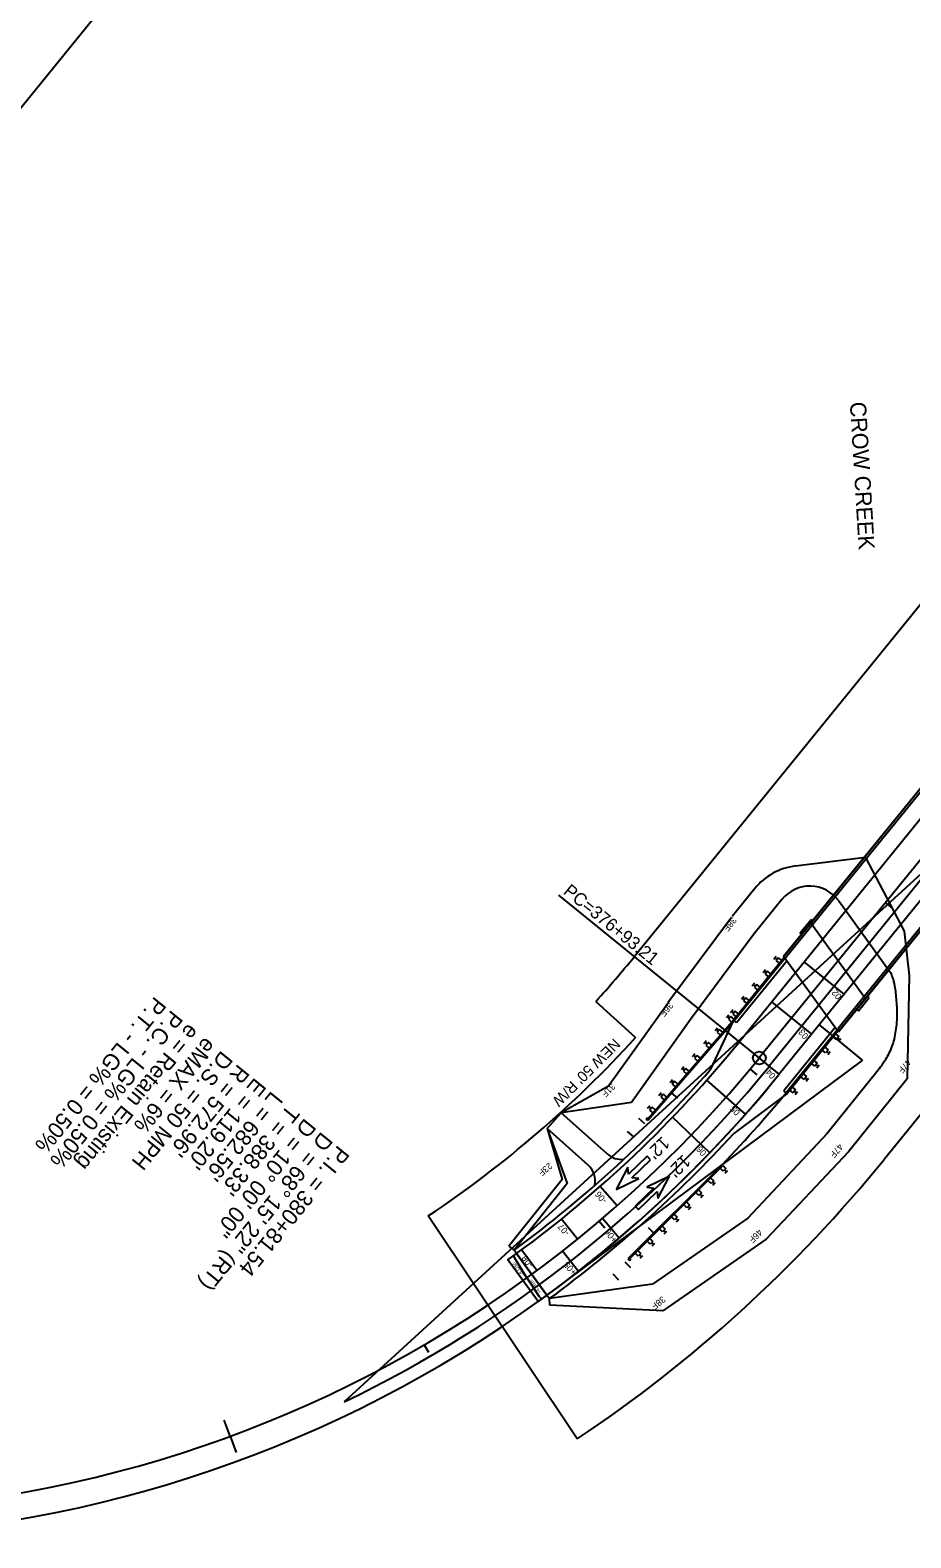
# Model space of a CAD drawing. Extents: x 144 to 1452322, y 4017 to 1128039.
# Drawn here: x 1450309 to 1450719, y 1126638 to 1127341 of the extents above; entities that cross this region are included whole.
import ezdxf

# ---------------------------------------------------------------- set-up
doc = ezdxf.new("R2010")
doc.units = 0
for name, color, linetype in [('BR_CONCRETE', 7, 'Continuous'), ('BR_PROPOSED_TRAVELWAY', 7, 'Continuous'), ('RD_HC_Cl', 7, 'Continuous'), ('RD_HC_Data', 7, 'Continuous'), ('RD_HC_Data_Tic', 7, 'Continuous'), ('RD_PD_ALT1_TX', 7, 'Continuous'), ('RD_PD_BOC', 7, 'Continuous'), ('RD_PD_CstnLmt', 7, 'Continuous'), ('RD_PD_CstnLmt_TX', 7, 'Continuous'), ('RD_PD_DR_ErosCtrl', 7, 'Continuous'), ('RD_PD_Driveway', 7, 'Continuous'), ('RD_PD_EOP', 7, 'Continuous'), ('RD_PD_Final_TrvlWay', 7, 'Continuous'), ('RD_PD_Final_TX', 7, 'Continuous'), ('RD_PD_FOC', 7, 'Continuous'), ('RD_PD_GR', 7, 'Continuous'), ('RD_PD_PaveShd', 7, 'Continuous'), ('RD_PD_RW', 7, 'Continuous'), ('RD_SHT_ShtClip', 7, 'Continuous'), ('RD_Sketch8', 7, 'Continuous'), ('RD_Sketch9', 7, 'Continuous'), ('RD_SMD_Locator', 7, 'Continuous'), ('RD_TX_Pipe_ElevEX', 7, 'Continuous')]:
    doc.layers.add(name, color=color, linetype=linetype)

# ---------------------------------------------------------------- blocks, each defined once
blk = doc.blocks.new('Guardrail_MTBBC3_Transition')
at = {"layer": 'RD_PD_GR'}
for p, q in [((37, 0.5), (0, 0.5)), ((0, 0.5), (0, 0)), ((0, 0), (37, 0)), ((3.525, 3.75), (1.775, 3.75)), ((1.775, 0.5), (1.775, 2.5)), ((1.775, 2.5), (3.525, 2.5)), ((3.525, 0.5), (1.775, 0.5)), ((2.65, 2.5), (2.65, 3.75)), ((3.525, 2.5), (3.525, 0.5)), ((11.525, 3.75), (9.775, 3.75)), ((9.775, 0.5), (9.775, 2.5)), ((9.775, 2.5), (11.525, 2.5)), ((11.525, 0.5), (9.775, 0.5)), ((10.65, 2.5), (10.65, 3.75)), ((11.525, 2.5), (11.525, 0.5)), ((19.525, 3.75), (17.775, 3.75)), ((17.775, 0.5), (17.775, 2.5)), ((17.775, 2.5), (19.525, 2.5)), ((19.525, 0.5), (17.775, 0.5)), ((18.65, 2.5), (18.65, 3.75)), ((19.525, 2.5), (19.525, 0.5)), ((27.525, 3.75), (25.775, 3.75)), ((25.775, 0.5), (25.775, 2.5)), ((25.775, 2.5), (27.525, 2.5)), ((27.525, 0.5), (25.775, 0.5)), ((26.65, 2.5), (26.65, 3.75)), ((27.525, 2.5), (27.525, 0.5)), ((30.65, 0.5), (30.65, 0)), ((35.525, 3.75), (33.775, 3.75)), ((33.775, 0.5), (33.775, 2.5)), ((33.775, 2.5), (35.525, 2.5)), ((35.525, 0.5), (33.775, 0.5)), ((34.65, 2.5), (34.65, 3.75)), ((35.525, 2.5), (35.525, 0.5)), ((37, 0), (37, 0.5))]:
    blk.add_line(p, q, dxfattribs=at)
blk = doc.blocks.new('Guardrail_MT3_Leading_with_Buffer')
at = {"layer": 'RD_PD_GR'}
for p, q in [((1.63, 3.8), (-0.12, 3.75)), ((-0.08, 2.5), (1.67, 2.56)), ((-0.02, 0.5), (-0.08, 2.5)), ((60.95, 2.47), (-0.02, 0.5)), ((1.73, 0.56), (-0.02, 0.5)), ((-0.02, 0.5), (0, 0)), ((0, 0), (61.97, 2)), ((0.79, 2.53), (0.75, 3.78)), ((1.67, 2.56), (1.73, 0.56)), ((9.62, 4.06), (7.87, 4.01)), ((7.92, 2.76), (9.66, 2.81)), ((7.98, 0.76), (7.92, 2.76)), ((9.73, 0.81), (7.98, 0.76)), ((8.79, 2.78), (8.75, 4.03)), ((9.66, 2.81), (9.73, 0.81)), ((17.62, 4.32), (15.87, 4.26)), ((15.91, 3.01), (17.66, 3.07)), ((15.98, 1.02), (15.91, 3.01)), ((17.72, 1.07), (15.98, 1.02)), ((16.79, 3.04), (16.75, 4.29)), ((17.66, 3.07), (17.72, 1.07)), ((25.62, 4.58), (23.87, 4.52)), ((23.91, 3.27), (25.66, 3.33)), ((23.97, 1.27), (23.91, 3.27)), ((25.72, 1.33), (23.97, 1.27)), ((24.78, 3.3), (24.74, 4.55)), ((25.66, 3.33), (25.72, 1.33)), ((33.61, 4.84), (31.86, 4.78)), ((31.9, 3.53), (33.65, 3.59)), ((31.97, 1.53), (31.9, 3.53)), ((33.72, 1.59), (31.97, 1.53)), ((32.78, 3.56), (32.74, 4.81)), ((33.65, 3.59), (33.72, 1.59)), ((41.61, 5.09), (39.86, 5.04)), ((39.9, 3.79), (41.65, 3.84)), ((39.96, 1.79), (39.9, 3.79)), ((41.71, 1.85), (39.96, 1.79)), ((40.77, 3.82), (40.73, 5.07)), ((41.65, 3.84), (41.71, 1.85)), ((45.1, -2.3), (44.98, 1.45)), ((49.6, 5.35), (47.85, 5.3)), ((47.89, 4.05), (49.64, 4.1)), ((47.96, 2.05), (47.89, 4.05)), ((49.71, 2.1), (47.96, 2.05)), ((48.77, 4.07), (48.73, 5.32)), ((49.64, 4.1), (49.71, 2.1)), ((57.6, 5.61), (55.85, 5.55)), ((55.89, 4.3), (57.64, 4.36)), ((55.95, 2.31), (55.89, 4.3)), ((57.7, 2.36), (55.95, 2.31)), ((56.76, 4.33), (56.72, 5.58)), ((57.64, 4.36), (57.7, 2.36)), ((61.94, 3), (60.94, 2.97)), ((60.94, 2.97), (60.95, 2.47)), ((61.97, 2), (61.94, 3)), ((63.97, 2.06), (63.85, 5.81)), ((71.96, 2.32), (71.84, 6.07))]:
    blk.add_line(p, q, dxfattribs=at)

msp = doc.modelspace()

# ---------------------------------------------------------------- linework, layer by layer
at = {"layer": 'BR_CONCRETE'}
for p, q in [((1450779.97, 1127056.48), (1450660.19, 1126908.99)), ((1450780.02, 1127056.41), (1450660.24, 1126908.92)), ((1450780.04, 1127054.84), (1450661.52, 1126908.91)), ((1450804.15, 1127021.34), (1450685.63, 1126875.41)), ((1450805.43, 1127021.33), (1450685.64, 1126873.85)), ((1450805.48, 1127021.26), (1450685.7, 1126873.78)), ((1450698.3, 1126889.3), (1450672.8, 1126924.52)), ((1450685.7, 1126873.78), (1450660.19, 1126908.99)), ((1450661.52, 1126908.91), (1450660.69, 1126908.29)), ((1450685.63, 1126875.41), (1450685.19, 1126874.48))]:
    msp.add_line(p, q, dxfattribs=at)
for points in [[(1450673, 1126926.35), (1450673.78, 1126925.72), (1450668.73, 1126919.51), (1450667.96, 1126920.14)], [(1450700.06, 1126889.88), (1450699.28, 1126890.51), (1450694.24, 1126884.3), (1450695.02, 1126883.67)]]:
    msp.add_lwpolyline(points, close=True, dxfattribs=at)
at = {"layer": 'BR_PROPOSED_TRAVELWAY'}
for p, q in [((1450785.44, 1127048.93), (1450665.65, 1126901.45)), ((1450800.02, 1127028.81), (1450680.23, 1126881.32))]:
    msp.add_line(p, q, dxfattribs=at)
at = {"layer": 'RD_HC_Cl'}
msp.add_line((1450930.04, 1127207.93), (1450648.85, 1126861.73), dxfattribs=at)
msp.add_arc((1450204.11, 1127222.95), 572.96, 252.66042, 320.91666, dxfattribs=at)
at = {"layer": 'RD_HC_Data'}
msp.add_line((1450648.85, 1126861.73), (1450555.35, 1126937.67), dxfattribs=at)
for radius in [3, 0.282]:
    msp.add_circle((1450648.85, 1126861.73), radius, dxfattribs=at)
at = {"layer": 'RD_HC_Data_Tic'}
for p, q in [((1450707.62, 1126934.08), (1450710.72, 1126931.56)), ((1450644.54, 1126856.48), (1450647.62, 1126853.92)), ((1450574.21, 1126785.57), (1450576.8, 1126782.51)), ((1450492.64, 1126727.94), (1450494.65, 1126724.49)), ((1450402.3, 1126685.36), (1450399.53, 1126692.87)), ((1450402.3, 1126685.36), (1450405.07, 1126677.85))]:
    msp.add_line(p, q, dxfattribs=at)
at = {"layer": 'RD_PD_ALT1_TX'}
for p, q in [((1450688.43, 1126891.42), (1450669.8, 1126906.55)), ((1450673.3, 1126872.79), (1450654.67, 1126887.92)), ((1450658.17, 1126854.16), (1450639.54, 1126869.29)), ((1450642.33, 1126835.47), (1450624.35, 1126851.37)), ((1450625.72, 1126817.46), (1450608.42, 1126834.1)), ((1450582.54, 1126792.75), (1450574.62, 1126801.76)), ((1450564.19, 1126777.28), (1450556.65, 1126786.62)), ((1450583.52, 1126777.73), (1450575.74, 1126786.86)), ((1450545.22, 1126762.59), (1450538.07, 1126772.24)), ((1450564.54, 1126762.23), (1450557.15, 1126771.68))]:
    msp.add_line(p, q, dxfattribs=at)
at = {"layer": 'RD_PD_BOC'}
for p, q in [((1450660.49, 1126908.57), (1450636.74, 1126879.33)), ((1450685.39, 1126874.2), (1450661.81, 1126845.16))]:
    msp.add_line(p, q, dxfattribs=at)
at = {"layer": 'RD_PD_CstnLmt'}
for p, q in [((1450659.34, 1126935.63), (1450646.31, 1126919.46)), ((1450685.9, 1126934.94), (1450709.57, 1126902.25)), ((1450646.31, 1126919.46), (1450616.72, 1126879.63)), ((1450616.72, 1126879.63), (1450589.22, 1126841.02)), ((1450703.64, 1126855.26), (1450680.53, 1126826.54)), ((1450589.22, 1126841.02), (1450556.49, 1126836.18)), ((1450549.95, 1126828.88), (1450559.26, 1126803.24)), ((1450680.53, 1126826.54), (1450643.57, 1126787.11)), ((1450559.26, 1126803.24), (1450534.53, 1126772.11)), ((1450643.57, 1126787.11), (1450599.03, 1126756.23)), ((1450599.03, 1126756.23), (1450551.08, 1126749.52))]:
    msp.add_line(p, q, dxfattribs=at)
msp.add_arc((1450672.36, 1126925.13), 16.72, 35.91666, 141.10348, dxfattribs=at)
msp.add_spline([(1450709.57, 1126902.25), (1450710.83, 1126899.44), (1450711.83, 1126895.42), (1450712.36, 1126891.97), (1450712.57, 1126889.38), (1450712.98, 1126881.54), (1450712.71, 1126877.34), (1450712.23, 1126873.39), (1450711.37, 1126869.64), (1450710.36, 1126866.38), (1450708.87, 1126863.16), (1450707.31, 1126860.4), (1450705.71, 1126858.12), (1450703.64, 1126855.26)], degree=3, dxfattribs=at)
at = {"layer": 'RD_PD_DR_ErosCtrl'}
for p, q in [((1450698.36, 1126955.24), (1450665.68, 1126951.23)), ((1450698.36, 1126955.24), (1450716.42, 1126920.91)), ((1450646.75, 1126940.71), (1450636.19, 1126927.62)), ((1450635.87, 1126927.21), (1450606.29, 1126887.38)), ((1450716.42, 1126920.91), (1450718.73, 1126900.2)), ((1450718.73, 1126900.2), (1450717.73, 1126852.04)), ((1450606.14, 1126887.17), (1450578.63, 1126848.56)), ((1450578.63, 1126848.56), (1450556.49, 1126836.18)), ((1450717.73, 1126852.04), (1450690.35, 1126818)), ((1450549.95, 1126828.88), (1450556.91, 1126805.1)), ((1450690.35, 1126818), (1450652.11, 1126777.21)), ((1450556.91, 1126805.1), (1450532.18, 1126773.97)), ((1450652.11, 1126777.21), (1450603.9, 1126743.79)), ((1450532.18, 1126773.97), (1450534.53, 1126772.11)), ((1450551.19, 1126746.51), (1450551.08, 1126749.52)), ((1450603.9, 1126743.79), (1450551.19, 1126746.51))]:
    msp.add_line(p, q, dxfattribs=at)
msp.add_arc((1450669.18, 1126922.63), 28.82, 96.98174, 141.12904, dxfattribs=at)
at = {"layer": 'RD_PD_Driveway'}
for p, q in [((1450549.95, 1126828.88), (1450556.49, 1126836.18)), ((1450577.9, 1126817), (1450556.49, 1126836.18)), ((1450569.02, 1126811.8), (1450549.95, 1126828.88))]:
    msp.add_line(p, q, dxfattribs=at)
for centre, start, end in [((1450584.57, 1126824.45), 228.14616, 276.49305), ((1450562.34, 1126804.35), 347.73828, 48.14616)]:
    msp.add_arc(centre, 10, start, end, dxfattribs=at)
at = {"layer": 'RD_PD_EOP'}
for p, q in [((1450661.71, 1126906.9), (1450638.29, 1126878.07)), ((1450638.29, 1126878.07), (1450636.74, 1126879.33)), ((1450684.18, 1126875.87), (1450660.26, 1126846.42)), ((1450661.81, 1126845.16), (1450660.26, 1126846.42))]:
    msp.add_line(p, q, dxfattribs=at)
at = {"layer": 'RD_PD_Final_TrvlWay'}
for p, q in [((1450665.65, 1126901.45), (1450639.54, 1126869.29)), ((1450680.23, 1126881.32), (1450658.17, 1126854.16)), ((1450549.9, 1126751.14), (1450535.71, 1126770.49))]:
    msp.add_line(p, q, dxfattribs=at)
for radius in [560.96, 584.96]:
    msp.add_arc((1450204.11, 1127222.95), radius, 306.23764, 320.91666, dxfattribs=at)
at = {"layer": 'RD_PD_Final_TX'}
for p, q in [((1450587.64, 1126810.84), (1450582.1, 1126800.38)), ((1450587.9, 1126807.54), (1450587.64, 1126810.84)), ((1450596.53, 1126815.88), (1450587.9, 1126807.54)), ((1450589.46, 1126805.92), (1450598.09, 1126814.26)), ((1450598.09, 1126814.26), (1450596.53, 1126815.88)), ((1450582.1, 1126800.38), (1450592.74, 1126805.55)), ((1450592.74, 1126805.55), (1450589.46, 1126805.92)), ((1450607.04, 1126806.6), (1450596.39, 1126801.43)), ((1450601.5, 1126796.14), (1450607.04, 1126806.6)), ((1450599.67, 1126801.05), (1450591.04, 1126792.71)), ((1450592.61, 1126791.1), (1450601.24, 1126799.43)), ((1450596.39, 1126801.43), (1450599.67, 1126801.05)), ((1450601.24, 1126799.43), (1450601.5, 1126796.14)), ((1450591.04, 1126792.71), (1450592.61, 1126791.1))]:
    msp.add_line(p, q, dxfattribs=at)
at = {"layer": 'RD_PD_FOC'}
for p, q in [((1450660.8, 1126908.15), (1450637.13, 1126879.01)), ((1450685.09, 1126874.62), (1450661.42, 1126845.48))]:
    msp.add_line(p, q, dxfattribs=at)
at = {"layer": 'RD_PD_GR'}
msp.add_arc((1450204.11, 1127222.95), 592.96, 316.11482, 320.91666, dxfattribs=at)
at = {"layer": 'RD_PD_PaveShd'}
for p, q in [((1450636.74, 1126879.33), (1450625.94, 1126856.22)), ((1450661.81, 1126845.16), (1450636.96, 1126826.52)), ((1450535.71, 1126770.49), (1450534.53, 1126772.11)), ((1450549.9, 1126751.14), (1450551.08, 1126749.52))]:
    msp.add_line(p, q, dxfattribs=at)
for radius, end in [(558.96, 318.99769), (586.96, 317.51498)]:
    msp.add_arc((1450204.11, 1127222.95), radius, 306.23764, end, dxfattribs=at)
at = {"layer": 'RD_PD_RW'}
for p, q in [((1450775.49, 1127136.61), (1450590.64, 1126909.01)), ((1450891.92, 1127042.04), (1450707.07, 1126814.44)), ((1450572.63, 1126888.06), (1450591.13, 1126871.24)), ((1450563.98, 1126684.11), (1450494.55, 1126788.06))]:
    msp.add_line(p, q, dxfattribs=at)
for radius, start, end in [(497.96, 317.73764, 320.91666), (522.96, 303.73764, 317.73764), (647.96, 303.73764, 320.91666)]:
    msp.add_arc((1450204.11, 1127222.95), radius, start, end, dxfattribs=at)
at = {"layer": 'RD_SHT_ShtClip'}
msp.add_line((1449765.76, 1126641.3), (1450900.57, 1128038.52), dxfattribs=at)
at = {"layer": 'RD_Sketch8'}
for q in [(1450676.82, 1126877.12), (1450553.63, 1126753.9)]:
    msp.add_line((1450697, 1126860.73), q, dxfattribs=at)
msp.add_arc((1450204.11, 1127222.95), 584.96, 252.66042, 320.91666, dxfattribs=at)
at = {"layer": 'RD_Sketch9'}
for p, q in [((1450819.45, 1127062.25), (1450653.51, 1126857.94)), ((1450835.36, 1127049.33), (1450455.42, 1126701.38))]:
    msp.add_line(p, q, dxfattribs=at)
msp.add_arc((1450204.11, 1127222.95), 578.96, 295.7266, 320.91666, dxfattribs=at)
at = {"layer": 'RD_SMD_Locator'}
msp.add_circle((1450648.85, 1126861.73), 0.15, dxfattribs=at)
at = {"layer": 'RD_TX_Pipe_ElevEX'}
for q in [(1450534.22, 1126769.4), (1450546.3, 1126750.52)]:
    msp.add_line((1450540.52, 1126759.15), q, dxfattribs=at)
msp.add_lwpolyline([(1450549.9, 1126751.14), (1450545.86, 1126748.18), (1450531.67, 1126767.54), (1450535.71, 1126770.49)], close=True, dxfattribs=at)
msp.add_lwpolyline([(1450547.44, 1126749.34), (1450546.77, 1126750.04), (1450546.3, 1126750.52), (1450544.56, 1126753.12), (1450539.8, 1126760.24), (1450538.07, 1126763.07), (1450534.22, 1126769.4)], dxfattribs=at)

# ---------------------------------------------------------------- block references
at = {"layer": 'RD_SHT_ShtClip'}
for name, p, yscale, rotation in [('Guardrail_MTBBC3_Transition', (1450660.8, 1126908.15), -1.0000000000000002, -129.08333510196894), ('Guardrail_MT3_Leading_with_Buffer', (1450637.47, 1126879.43), -1, -129.08333510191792)]:
    msp.add_blockref(name, p, dxfattribs=dict(at, yscale=yscale, rotation=rotation))
for name, p, rotation in [('Guardrail_MTBBC3_Transition', (1450685.09, 1126874.62), -129.08333510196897), ('Guardrail_MTBBC3_Transition', (1450685.09, 1126874.62), -129.08333510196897), ('Guardrail_MT3_Leading_with_Buffer', (1450631.47, 1126811.9), -136.87578506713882)]:
    msp.add_blockref(name, p, dxfattribs=dict(at, rotation=rotation))

# ---------------------------------------------------------------- texts
at = {"layer": 'RD_HC_Data'}
for s, height, rotation, p in [('CROW CREEK', 7.5, 273.4397, (1450691.03, 1127167.45)), ('PC=376+93.21', 6, 320.91666, (1450557.08, 1126938.64)), ('P.T. - LG% = 0.50%', 7.5, 230.91666, (1450367.18, 1126890.78)), ('P.C. - LG% = 0.50%', 7.5, 230.91666, (1450374.94, 1126884.47)), ('e = Retain Existing', 7.5, 230.91666, (1450382.71, 1126878.17)), ('eMAX = 6%', 7.5, 230.91666, (1450390.47, 1126871.86)), ('D.S. = 50 MPH', 7.5, 230.91666, (1450398.23, 1126865.56)), ("R = 572.96'", 7.5, 230.91666, (1450405.99, 1126859.25)), ("E = 119.20'", 7.5, 230.91666, (1450413.76, 1126852.95)), ("L = 682.56'", 7.5, 230.91666, (1450421.52, 1126846.64)), ("T = 388.33'", 7.5, 230.91666, (1450429.28, 1126840.34)), ('D = 10%%d 00\' 00"', 7.5, 230.91666, (1450437.04, 1126834.04)), ('D', 7.5, 230.91666, (1450444.81, 1126827.73)), ('    = 68%%d 15\' 22" (RT)', 7.5, 230.91666, (1450444.81, 1126827.73)), ('P.I. = 380+81.54', 7.5, 230.91666, (1450452.57, 1126821.43))]:
    msp.add_text(s, height=height, rotation=rotation, dxfattribs=at).set_placement(p)
at = {"layer": 'RD_PD_ALT1_TX'}
for s, rotation, p in [('02', 130.23764, (1450687.44, 1126890.56)), ('03', 130.23764, (1450671.96, 1126872.08)), ('04', 130.23764, (1450656.71, 1126853.55)), ('05', 130.23764, (1450640.12, 1126836.45)), ('06', 130.23764, (1450624.44, 1126817.54)), ('-06', 130.23764, (1450578.06, 1126795.46)), ('-07', 130.23764, (1450560.68, 1126780.4)), ('+06', 126.23764, (1450582.88, 1126776.96)), ('-08', 126.23764, (1450543.72, 1126765.42)), ('+05', 130.23764, (1450564.02, 1126761.97))]:
    msp.add_text(s, height=3, rotation=rotation, dxfattribs=at).set_placement(p)
at = {"layer": 'RD_PD_CstnLmt_TX'}
for s, rotation, p in [('38F', 230.91666, (1450636.22, 1126927.65)), ('36F', 230.23764, (1450606.73, 1126887.94)), ('47F', 230.91666, (1450717.65, 1126861.51)), ('31F', 225.23764, (1450579.99, 1126850.17)), ('47F', 230.23764, (1450685.91, 1126822.06)), ('23F', 220.23764, (1450550.86, 1126813.16)), ('46F', 225.23764, (1450648.54, 1126782.18)), ('38F', 220.23764, (1450603.56, 1126750.89))]:
    msp.add_text(s, height=3, rotation=rotation, dxfattribs=at).set_placement(p)
at = {"layer": 'RD_PD_Final_TX'}
for p in [(1450603.64, 1126825.59), (1450613.36, 1126817.12)]:
    msp.add_text("12'", height=6, rotation=223.99476, dxfattribs=at).set_placement(p)
at = {"layer": 'RD_PD_RW'}
msp.add_text("NEW 50' R/W", height=5, rotation=224.95508, dxfattribs=at).set_placement((1450581.02, 1126871.2))
at = {"layer": 'RD_TX_Pipe_ElevEX'}
for s, p in [('-8.1250', (1450539.01, 1126761)), ('+4.2695', (1450547.34, 1126752.55))]:
    msp.add_text(s, height=1.5, rotation=126.23764, dxfattribs=at).set_placement(p)

doc.saveas('drawing.dxf')
